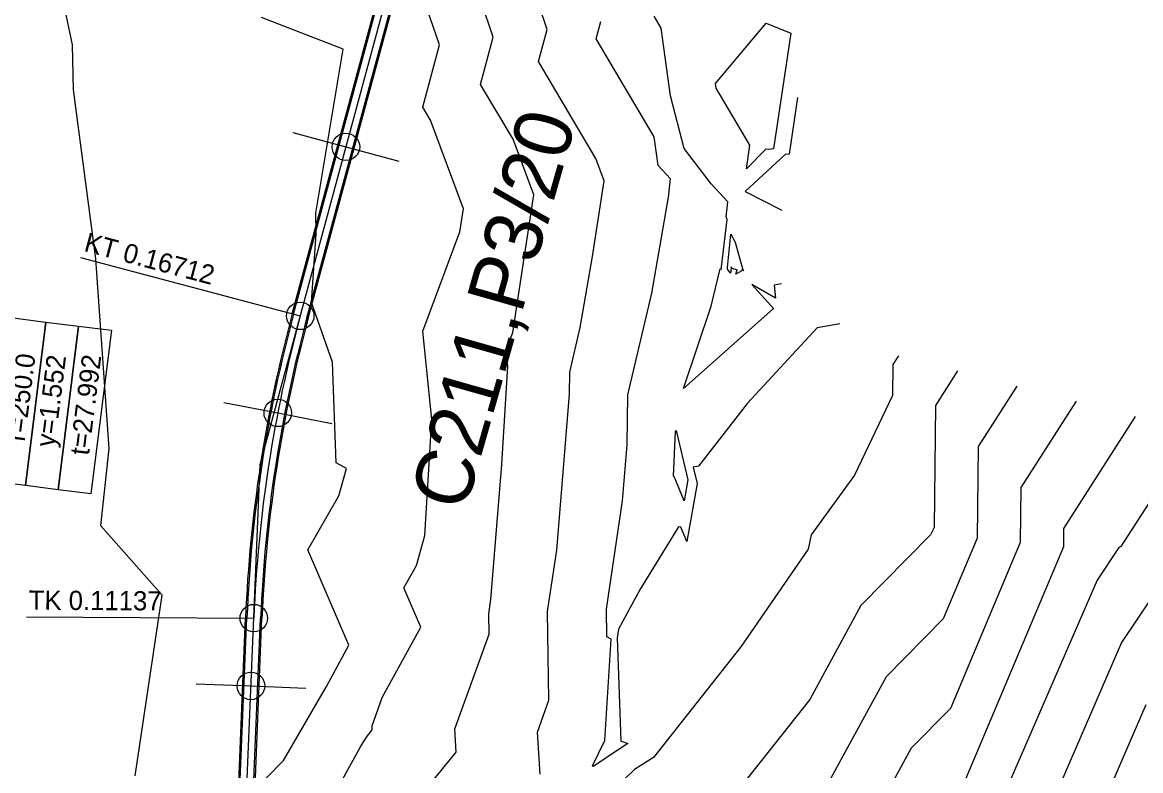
# Model space of a CAD drawing. Extents: x -549394 to -546608, y -1037055 to -1033629.
# Drawn here: x -547937.2 to -547733.5, y -1034518.7 to -1034382.6 of the extents above; entities that cross this region are included whole.
import ezdxf

# ---------------------------------------------------------------- set-up
doc = ezdxf.new("R2010")
doc.units = 0
for name, color, linetype in [('hlavni_vrst', 7, 'Continuous'), ('norm_vrst', 7, 'Continuous'), ('POLYGONY_SITUACE_PO', 7, 'Continuous'), ('u_sirka_1_0m', 7, 'Continuous'), ('x_navrh_C211', 7, 'Continuous'), ('x_osa_C211', 7, 'Continuous'), ('x_popis_oblouky_C211', 7, 'Continuous'), ('x_popis_pricne_rezy_C211', 7, 'Continuous'), ('x_popis_velky_C211', 7, 'Continuous')]:
    doc.layers.add(name, color=color, linetype=linetype)

msp = doc.modelspace()

# ---------------------------------------------------------------- linework, layer by layer
at = {"layer": 'hlavni_vrst'}
for p, q in [((-547851.42, -1034385.28), (-547853.56, -1034378.97)), ((-547853.71, -1034393.89), (-547851.42, -1034385.28)), ((-547847.78, -1034403.88), (-547853.71, -1034393.89)), ((-547844.03, -1034413.98), (-547847.78, -1034403.88)), ((-547847.85, -1034439), (-547844.03, -1034413.98)), ((-547808.1, -1034427.23), (-547808.09, -1034427.11)), ((-547808.1, -1034427.23), (-547808.1, -1034427.23)), ((-547808.09, -1034427.23), (-547808.1, -1034427.23)), ((-547808.09, -1034427.11), (-547808.03, -1034427.23)), ((-547808.03, -1034427.23), (-547808.09, -1034427.23)), ((-547849.06, -1034442.26), (-547847.85, -1034439)), ((-547848.77, -1034445.16), (-547849.06, -1034442.26)), ((-547849.84, -1034463.05), (-547848.77, -1034445.16)), ((-547766.85, -1034446.01), (-547770.88, -1034452.32)), ((-547770.88, -1034452.32), (-547771.13, -1034474.49)), ((-547851.85, -1034487.64), (-547849.84, -1034463.05)), ((-547771.13, -1034474.49), (-547771.77, -1034475.85)), ((-547771.77, -1034475.85), (-547784.47, -1034488.72)), ((-547725.04, -1034477.54), (-547737, -1034495.44)), ((-547852.24, -1034490.22), (-547851.85, -1034487.64)), ((-547784.47, -1034488.72), (-547793.79, -1034505.78)), ((-547852.18, -1034493.94), (-547852.24, -1034490.22)), ((-547858.43, -1034511.17), (-547852.18, -1034493.94)), ((-547737, -1034495.44), (-547755.79, -1034538.71)), ((-547793.79, -1034505.78), (-547811.09, -1034527.65)), ((-547858.15, -1034515.37), (-547858.43, -1034511.17)), ((-547863.82, -1034522.3), (-547858.15, -1034515.37))]:
    msp.add_line(p, q, dxfattribs=at)
at = {"layer": 'norm_vrst'}
for p, q in [((-547861.22, -1034386.68), (-547864.04, -1034378.36)), ((-547841.62, -1034383.88), (-547843.07, -1034379.57)), ((-547928.01, -1034386.66), (-547929.16, -1034381.23)), ((-547878.73, -1034387.48), (-547893.6, -1034381.7)), ((-547820.82, -1034383.64), (-547822.11, -1034381.45)), ((-547843.17, -1034389.74), (-547841.62, -1034383.88)), ((-547832.64, -1034385.6), (-547831.82, -1034382.47)), ((-547819.13, -1034395.97), (-547820.82, -1034383.64)), ((-547810.96, -1034393.73), (-547801.74, -1034382.73)), ((-547801.74, -1034382.73), (-547797.24, -1034384.54)), ((-547822.08, -1034403.4), (-547832.64, -1034385.6)), ((-547797.24, -1034384.54), (-547800.38, -1034405.64)), ((-547927.84, -1034394.89), (-547928.01, -1034386.66)), ((-547883.74, -1034417.3), (-547878.73, -1034387.48)), ((-547864.24, -1034398.03), (-547861.22, -1034386.68)), ((-547832.72, -1034407.35), (-547843.17, -1034389.74)), ((-547810.79, -1034394.58), (-547810.96, -1034393.73)), ((-547923.78, -1034425.62), (-547927.84, -1034394.89)), ((-547816.64, -1034405.56), (-547819.13, -1034395.97)), ((-547804.67, -1034404.96), (-547810.79, -1034394.58)), ((-547862.83, -1034400.4), (-547864.24, -1034398.03)), ((-547795.99, -1034396.24), (-547797.53, -1034406.56)), ((-547856.85, -1034416.52), (-547862.83, -1034400.4)), ((-547821.36, -1034408.67), (-547822.08, -1034403.4)), ((-547811.74, -1034411.97), (-547816.64, -1034405.56)), ((-547805.31, -1034409.22), (-547804.67, -1034404.96)), ((-547801.76, -1034405.66), (-547805.31, -1034409.22)), ((-547801.21, -1034405.71), (-547801.76, -1034405.66)), ((-547800.38, -1034405.64), (-547801.21, -1034405.71)), ((-547831.2, -1034411.45), (-547832.72, -1034407.35)), ((-547798.24, -1034406.63), (-547805.53, -1034413.38)), ((-547797.53, -1034406.56), (-547798.24, -1034406.63)), ((-547819.14, -1034411.06), (-547821.36, -1034408.67)), ((-547833.31, -1034425.23), (-547831.2, -1034411.45)), ((-547819.48, -1034414.43), (-547819.14, -1034411.06)), ((-547808.7, -1034415.26), (-547811.74, -1034411.97)), ((-547822.51, -1034431.85), (-547819.48, -1034414.43)), ((-547805.53, -1034413.38), (-547798.84, -1034416.8)), ((-547857.49, -1034420.69), (-547856.85, -1034416.52)), ((-547808.98, -1034418.01), (-547808.7, -1034415.26)), ((-547883.65, -1034421.09), (-547883.74, -1034417.3)), ((-547809.86, -1034427.06), (-547808.83, -1034418.48)), ((-547808.83, -1034418.48), (-547808.98, -1034418.01)), ((-547884.5, -1034433.57), (-547883.65, -1034421.09)), ((-547864.21, -1034438.77), (-547857.49, -1034420.69)), ((-547808.76, -1034427.19), (-547808.14, -1034421.14)), ((-547808.14, -1034421.14), (-547807.38, -1034422.59)), ((-547807.38, -1034422.59), (-547805.94, -1034427.64)), ((-547921.36, -1034460.11), (-547923.78, -1034425.62)), ((-547835.56, -1034438.13), (-547833.31, -1034425.23)), ((-547811.74, -1034434.26), (-547810.11, -1034427.46)), ((-547810.11, -1034427.46), (-547809.86, -1034427.5)), ((-547809.86, -1034427.5), (-547809.86, -1034427.06)), ((-547808.78, -1034427.51), (-547808.73, -1034427.2)), ((-547808.19, -1034428.24), (-547808.78, -1034427.51)), ((-547808.73, -1034427.2), (-547808.76, -1034427.19)), ((-547808.08, -1034427.33), (-547808.19, -1034428.24)), ((-547808.07, -1034427.33), (-547808.08, -1034427.33)), ((-547807.96, -1034427.34), (-547808.07, -1034427.33)), ((-547807.96, -1034427.34), (-547807.01, -1034427.61)), ((-547807.21, -1034428.43), (-547807, -1034427.63)), ((-547806.3, -1034427.96), (-547807.21, -1034428.43)), ((-547807.21, -1034428.43), (-547807.21, -1034428.43)), ((-547807.21, -1034428.43), (-547807.21, -1034428.43)), ((-547807.21, -1034428.43), (-547807.21, -1034428.43)), ((-547807.02, -1034427.63), (-547807.01, -1034427.61)), ((-547807, -1034427.63), (-547807.02, -1034427.63)), ((-547806.25, -1034427.66), (-547806.3, -1034427.96)), ((-547805.75, -1034427.74), (-547806.25, -1034427.66)), ((-547805.94, -1034427.64), (-547805.75, -1034427.74)), ((-547800.03, -1034432.81), (-547804.32, -1034430.28)), ((-547804.32, -1034430.28), (-547800.3, -1034434.75)), ((-547798.93, -1034430.17), (-547800.25, -1034430.4)), ((-547800.25, -1034430.4), (-547800.03, -1034432.81)), ((-547826.93, -1034450.37), (-547822.51, -1034431.85)), ((-547880.67, -1034444.43), (-547884.5, -1034433.57)), ((-547816.76, -1034449.19), (-547811.74, -1034434.26)), ((-547800.42, -1034434.72), (-547816.76, -1034449.19)), ((-547800.3, -1034434.75), (-547800.42, -1034434.72)), ((-547862.59, -1034454.86), (-547864.21, -1034438.77)), ((-547837.49, -1034446.25), (-547835.56, -1034438.13)), ((-547792.45, -1034438.21), (-547805.11, -1034451.9)), ((-547788.31, -1034437.48), (-547792.45, -1034438.21)), ((-547880.02, -1034462.74), (-547880.67, -1034444.43)), ((-547778.66, -1034444.85), (-547778.72, -1034450.47)), ((-547777.63, -1034443.25), (-547778.66, -1034444.85)), ((-547837.54, -1034450.22), (-547837.49, -1034446.25)), ((-547756.07, -1034448.78), (-547763.11, -1034459.78)), ((-547839.86, -1034478.64), (-547837.54, -1034450.22)), ((-547827.04, -1034459.45), (-547826.93, -1034450.37)), ((-547778.72, -1034450.47), (-547785.61, -1034465)), ((-547805.11, -1034451.9), (-547814.02, -1034463.33)), ((-547745.28, -1034451.54), (-547755.34, -1034467.25)), ((-547863.86, -1034475.99), (-547862.59, -1034454.86)), ((-547734.5, -1034454.3), (-547747.57, -1034474.72)), ((-547818.6, -1034465.16), (-547818.24, -1034457.04)), ((-547818.24, -1034457.04), (-547818.13, -1034456.86)), ((-547818.13, -1034456.86), (-547815.98, -1034465.84)), ((-547723.72, -1034457.07), (-547737.1, -1034477.97)), ((-547922.84, -1034474.19), (-547921.36, -1034460.11)), ((-547827.87, -1034469.65), (-547827.04, -1034459.45)), ((-547763.11, -1034459.78), (-547763.3, -1034476.45)), ((-547878.16, -1034463.79), (-547880.02, -1034462.74)), ((-547814.02, -1034463.33), (-547814.98, -1034463.51)), ((-547879.53, -1034468.75), (-547878.16, -1034463.79)), ((-547818.44, -1034465.23), (-547818.6, -1034465.16)), ((-547816.67, -1034469.63), (-547818.44, -1034465.23)), ((-547814.98, -1034463.51), (-547814.27, -1034466.48)), ((-547785.61, -1034465), (-547793.51, -1034475.83)), ((-547815.98, -1034465.84), (-547816.67, -1034469.63)), ((-547814.27, -1034466.48), (-547816.18, -1034477.05)), ((-547755.34, -1034467.25), (-547755.45, -1034477.25)), ((-547885.15, -1034478.58), (-547879.53, -1034468.75)), ((-547830.81, -1034489.4), (-547827.87, -1034469.65)), ((-547911.7, -1034486.8), (-547922.84, -1034474.19)), ((-547817.67, -1034474.42), (-547824.67, -1034485.71)), ((-547817.23, -1034474.44), (-547817.67, -1034474.42)), ((-547816.18, -1034477.05), (-547817.23, -1034474.44)), ((-547747.57, -1034474.72), (-547747.6, -1034478.05)), ((-547865.36, -1034481.45), (-547863.86, -1034475.99)), ((-547793.51, -1034475.83), (-547794.08, -1034478.48)), ((-547763.3, -1034476.45), (-547769.49, -1034491.15)), ((-547755.45, -1034477.25), (-547768.17, -1034507.42)), ((-547877.68, -1034495.9), (-547885.15, -1034478.58)), ((-547841.52, -1034489.81), (-547839.86, -1034478.64)), ((-547794.08, -1034478.48), (-547806.3, -1034496.24)), ((-547747.6, -1034478.05), (-547766.85, -1034523.7)), ((-547737.47, -1034478.15), (-547741.45, -1034484.11)), ((-547737.1, -1034477.97), (-547737.47, -1034478.15)), ((-547867.68, -1034485.5), (-547865.36, -1034481.45)), ((-547864.6, -1034492.63), (-547867.68, -1034485.5)), ((-547824.67, -1034485.71), (-547828.59, -1034493.03)), ((-547741.45, -1034484.11), (-547759.32, -1034525.27)), ((-547916.59, -1034519.69), (-547911.7, -1034486.8)), ((-547841.26, -1034505.95), (-547841.52, -1034489.81)), ((-547830.73, -1034494.39), (-547830.81, -1034489.4)), ((-547769.49, -1034491.15), (-547779.89, -1034501.69)), ((-547871.63, -1034505.46), (-547864.6, -1034492.63)), ((-547828.59, -1034493.03), (-547828.82, -1034494.6)), ((-547881.8, -1034503.43), (-547877.68, -1034495.9)), ((-547831.08, -1034513.25), (-547829.91, -1034494.8)), ((-547829.91, -1034494.8), (-547830.73, -1034494.39)), ((-547828.82, -1034494.6), (-547828.15, -1034513.4)), ((-547806.3, -1034496.24), (-547822.23, -1034516.38)), ((-547779.89, -1034501.69), (-547799.97, -1034538.43)), ((-547889.61, -1034516.88), (-547881.8, -1034503.43)), ((-547873.48, -1034510.57), (-547871.63, -1034505.46)), ((-547843.38, -1034511.76), (-547841.26, -1034505.95)), ((-547768.17, -1034507.42), (-547775.31, -1034514.66)), ((-547732.55, -1034506.77), (-547744.08, -1034533.33)), ((-547874.49, -1034512.65), (-547873.43, -1034511.35)), ((-547873.43, -1034511.35), (-547873.48, -1034510.57)), ((-547842.87, -1034519.39), (-547843.38, -1034511.76)), ((-547875.58, -1034514.45), (-547874.49, -1034512.65)), ((-547833.32, -1034517.85), (-547831.08, -1034513.25)), ((-547826.92, -1034513.81), (-547833.24, -1034518.02)), ((-547828.15, -1034513.4), (-547827.94, -1034513.44)), ((-547827.94, -1034513.44), (-547826.92, -1034513.81)), ((-547887.28, -1034535.44), (-547875.58, -1034514.45)), ((-547775.31, -1034514.66), (-547789.09, -1034539.88)), ((-547907.82, -1034535.35), (-547889.61, -1034516.88)), ((-547833.24, -1034518.02), (-547833.32, -1034517.85)), ((-547822.23, -1034516.38), (-547825.69, -1034518.53)), ((-547825.69, -1034518.53), (-547833.1, -1034525.66))]:
    msp.add_line(p, q, dxfattribs=at)
at = {"layer": 'POLYGONY_SITUACE_PO'}
for centre in [(-547886.55, -1034436.01), (-547895.02, -1034491)]:
    msp.add_circle(centre, 2.5, dxfattribs=at)
at = {"layer": 'u_sirka_1_0m'}
for centre in [(-547878.23, -1034405.25), (-547890.65, -1034453.66), (-547895.53, -1034503.34)]:
    msp.add_circle(centre, 2.5, dxfattribs=at)
at = {"layer": 'x_navrh_C211'}
for p, q in [((-547887.76, -1034435.68), (-547857.86, -1034325.17)), ((-547885.35, -1034436.34), (-547855.95, -1034327.68)), ((-547897.94, -1034531.38), (-547896.27, -1034490.94)), ((-547895.44, -1034531.49), (-547893.77, -1034491.05))]:
    msp.add_line(p, q, dxfattribs=at)
for points in [[(-547888, -1034435.62), (-547858.05, -1034324.91)], [(-547885.11, -1034436.4), (-547855.76, -1034327.93)], [(-547898.19, -1034531.37), (-547896.52, -1034490.93)], [(-547894.78, -1034521.5), (-547893.52, -1034491.06)]]:
    msp.add_lwpolyline(points, dxfattribs=at)
for radius in [251.5, 251.25, 248.75, 248.5]:
    msp.add_arc((-547645.23, -1034501.31), radius, 164.8602, 177.6366, dxfattribs=at)
at = {"layer": 'x_osa_C211'}
for points in [[(-547893.86, -1034463.03), (-547856.9, -1034326.42), (-547856.9, -1034326.42)], [(-547888.19, -1034592.9), (-547896.89, -1034536.29), (-547893.86, -1034463.03)]]:
    msp.add_lwpolyline(points, dxfattribs=at)
msp.add_arc((-547645.23, -1034501.31), 250, 164.8602, 177.6366, dxfattribs=at)
at = {"layer": 'x_popis_oblouky_C211'}
for points in [[(-547926.54, -1034425.38), (-547886.55, -1034436.01)], [(-547936.39, -1034490.75), (-547895.02, -1034491)]]:
    msp.add_lwpolyline(points, dxfattribs=at)
for points in [[(-547942.56, -1034466.14), (-547938.81, -1034436.37), (-547932.86, -1034437.12), (-547936.61, -1034466.89)], [(-547936.61, -1034466.89), (-547932.86, -1034437.12), (-547926.91, -1034437.87), (-547930.65, -1034467.64)], [(-547930.65, -1034467.64), (-547926.91, -1034437.87), (-547920.95, -1034438.62), (-547924.7, -1034468.38)]]:
    msp.add_lwpolyline(points, close=True, dxfattribs=at)
at = {"layer": 'x_popis_pricne_rezy_C211'}
for points in [[(-547887.88, -1034402.64), (-547878.23, -1034405.25), (-547868.58, -1034407.86)], [(-547900.47, -1034451.75), (-547890.65, -1034453.66), (-547880.83, -1034455.56)], [(-547905.52, -1034502.93), (-547895.53, -1034503.34), (-547885.54, -1034503.75)]]:
    msp.add_lwpolyline(points, dxfattribs=at)

# ---------------------------------------------------------------- texts
at = {"layer": 'x_popis_oblouky_C211'}
for s, rotation, p in [('KT 0.16712', 345.1109, (-547926.11, -1034424.17)), ('r=250.0', 82.8439, (-547936.74, -1034458.97)), ('y=1.552', 82.8439, (-547931.27, -1034460.01)), ('t=27.992', 82.8439, (-547925.05, -1034461.5)), ('TK 0.11137', 359.6557, (-547936.01, -1034489.47))]:
    msp.add_text(s, height=3.5, rotation=rotation, dxfattribs=at).set_placement(p)
at = {"layer": 'x_popis_velky_C211'}
msp.add_text('C211,P3/20', height=10.5, rotation=74.1138, dxfattribs=at).set_placement((-547856.54, -1034471.86))

doc.saveas('drawing.dxf')
